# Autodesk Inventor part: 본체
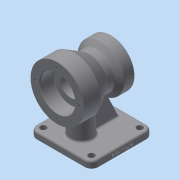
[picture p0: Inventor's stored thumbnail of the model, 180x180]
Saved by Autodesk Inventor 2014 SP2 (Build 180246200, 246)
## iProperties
Created: 2019-01
Part Number: 본체
Material: Generic
Document SubType Name: Modeling
Designer: 거성
Density: 1 g/cm^3
Appearance: Default
Author: 거성
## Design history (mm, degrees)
sketch "스케치1"
  geometry: L1 (44.102, 40)-(44.102, 15); L2 (39.102, -40)-(39.102, -25); L3 (39.102, -25)-(30.944, -18.154); L4 (30.944, -18.154)-(30.944, -7.791); L5 (30.944, -7.791)-(44.102, 15); L6 (20.102, 20)-(20.102, -23); L7 (24.102, -23)-(24.102, -40); L8 (30.102, 20)-(30.102, 40); L9 (4.102, -40)-(4.102, 40); L10 (20.102, -23)-(24.102, -23); L11 (20.102, 20)-(30.102, 20); L12 (30.102, 40)-(44.102, 40); L13 (39.102, -40)-(24.102, -40)
  constraints: 26 end point, 4 parallel, 3 perpendicular, 2 horizontal
  dimensions: "d2" = 25 distance of L1.start L1.end; "d3" = 30 deg angle of L4 L5; "d4" = 15 distance of L2.start L2.end; "d5" = 50 deg angle of L4 L3; "d6" = 52 diameter of L8 L9; "d7" = 32 diameter of L6 L9; "d8" = 40 diameter of L7 L9; "d9" = 80 vertical distance of L2.start L1.start; "d10" = 20 distance of L8.start L8.end; "d11" = 17 distance of L7.start L7.end; "d20" = 80 distance from line of L9.start L12; "d25" = 80 diameter of L1 L9; "d26" = 70 diameter of L2 L9; "d27" = 13.15845 distance between parallel lines of L4 L1; "d28" = 47.14102 distance from line of L9.end L5
revolve "회전1" sketch "스케치1" stored, may be unused: angle "d23" = 90 deg
sketch "스케치2"
  geometry: C1 r 40 at (0, 0) reference; C2 r 26 at (0, 0) reference; 1 further point
sketch "스케치3" dims "d24" = 66
  geometry: L1 (0, 0)-(0, 33); C1 r 26 at (0, 0) reference; 2 further points
  constraints: 2 coincident, 2 end point, 1 vertical, 1 vertical alignment, 2 other
hole "구멍1" sketch "스케치3" at (0, 33) diameter "d29" = 3.242; stored, may be unused: countersink angle "d33" = 90 deg, drill point angle "d35" = 118 deg; dims "d30" = 9, "d31" = 4, "d32" = 2, "d34" = 11
sketch "스케치4" dims "d39" = 55
  geometry: L1 (0, 0)-(0, 27.5); C1 r 35 at (0, 0) reference; 2 further points
  constraints: 2 coincident, 2 end point, 1 vertical, 1 vertical alignment, 2 other
hole "구멍2" sketch "스케치4" at (0, 27.5) diameter "d40" = 3.242; stored, may be unused: countersink angle "d44" = 90 deg, drill point angle "d46" = 118 deg; dims "d41" = 9, "d42" = 4, "d43" = 2, "d45" = 11
node "작업 평면1"
sketch "스케치7"
  geometry: L1 (-70, -36)-(-70, 36) reference; L2 (-70, 0)-(-70, -33.507); 1 further point
  constraints: 2 end point, 1 collinear, 1 midpoint
chamfer "모따기1" distance "d78" = 1; stored, may be unused: second distance "d79" = 2, angle "d80" = 45 deg
fillet "모깎기2" dims "d81" = 1
fillet "모깎기3" dims "d82" = 0.6
sketch "스케치11"
  geometry: L1 (-75.898, 0)-(-75.898, 35); L2 (-75.898, 35)-(-65.898, 35); L3 (-65.898, 35)-(-65.898, -57); L4 (-65.898, -57)-(-75.898, -57); L5 (-75.898, -57)-(-75.898, 0); L6 (-35.898, 40)-(44.102, 40) reference; L7 (44.102, 15)-(30.944, -7.791) reference; L8 (30.944, -7.791)-(30.944, -18.154) reference; L9 (30.944, -18.154)-(39.102, -25) reference; L10 (39.102, -25)-(39.102, -40) reference; L11 (39.102, -40)-(33.223, -40) reference; L12 (33.223, -40)-(33.223, -29) reference; L13 (33.223, -29)-(31.602, -28.026) reference; L14 (31.602, -28.026)-(29.981, -29) reference; L15 (29.981, -29)-(29.981, -40) reference; L16 (29.981, -40)-(25.102, -40) reference; L17 (25.102, -40)-(24.102, -39) reference; L18 (24.102, -39)-(24.102, -23.6) reference; L19 (23.502, -23)-(20.102, -23) reference; L20 (20.102, -23)-(20.102, 20) reference; L21 (20.102, 20)-(29.102, 20) reference; L22 (30.102, 21)-(30.102, 39) reference; L23 (30.102, 39)-(31.102, 40) reference; L24 (31.102, 40)-(35.481, 40) reference; L25 (35.481, 40)-(35.481, 29) reference; L26 (35.481, 29)-(37.102, 28.026) reference; L27 (37.102, 28.026)-(38.723, 29) reference; L28 (38.723, 29)-(38.723, 40) reference; L29 (38.723, 40)-(44.102, 40) reference; L30 (44.102, 40)-(44.102, 15) reference; L31 (-22.739, -7.791)-(-35.898, 15) reference; L32 (-35.898, 15)-(-35.898, 40) reference; L33 (-35.898, 40)-(-30.519, 40) reference; L34 (-30.519, 40)-(-30.519, 29) reference; L35 (-30.519, 29)-(-28.898, 28.026) reference; L36 (-28.898, 28.026)-(-27.277, 29) reference; L37 (-27.277, 29)-(-27.277, 40) reference; L38 (-27.277, 40)-(-22.898, 40) reference; L39 (-22.898, 40)-(-21.898, 39) reference; L40 (-21.898, 39)-(-21.898, 21) reference; L41 (-20.898, 20)-(-11.898, 20) reference; L42 (-11.898, 20)-(-11.898, -23) reference; L43 (-11.898, -23)-(-15.298, -23) reference; L44 (-15.898, -23.6)-(-15.898, -39) reference; L45 (-15.898, -39)-(-16.898, -40) reference; L46 (-16.898, -40)-(-21.777, -40) reference; L47 (-21.777, -40)-(-21.777, -29) reference; L48 (-21.777, -29)-(-23.398, -28.026) reference; L49 (-23.398, -28.026)-(-25.019, -29) reference; L50 (-25.019, -29)-(-25.019, -40) reference; L51 (-25.019, -40)-(-30.898, -40) reference; L52 (-30.898, -40)-(-30.898, -25) reference; L53 (-30.898, -25)-(-22.739, -18.154) reference; L54 (-22.739, -18.154)-(-22.739, -7.791) reference; L55 (31.102, 40)-(-22.898, 40) reference; L56 (4.102, 40)-(4.102, -40); L57 (5.723, -40)-(2.481, -40) reference; L58 (-75.898, 0)-(4.102, 0); A1 r 0.6 centre (23.502, -23.6) between (24.102, -23.6) and (23.502, -23) reference; A2 r 1 centre (29.102, 21) between (29.102, 20) and (30.102, 21) reference; A3 r 1 centre (-20.898, 21) between (-21.898, 21) and (-20.898, 20) reference; A4 r 0.6 centre (-15.298, -23.6) between (-15.298, -23) and (-15.898, -23.6) reference; 1 further point
  constraints: 14 end point, 3 midpoint, 2 parallel, 1 collinear, 1 perpendicular
  dimensions: "d92" = 5 distance between parallel lines of L2 L6; "d93" = 10 distance of L1.end L2.end; "d94" = 92 distance between parallel lines of L4 L2; "d127" = 80 distance of L1.start L58.end
extrude "돌출5" join sketch "스케치11" stored distance "d95" = 92; taper "d96" = 0 deg
sketch "스케치12"
  geometry: L1 (-65.898, -47)-(-16.918, -24.16); L2 (-16.918, -24.16)-(-16.918, -11); L3 (-30.898, -25)-(39.102, -25) reference; L4 (-16.918, -11)-(-65.898, -11); L5 (-65.898, 35)-(-65.898, -57) reference; L6 (-65.898, -47)-(-65.898, -11); L7 (-65.898, -57)-(-75.898, -57) reference; L8 (-65.898, 35)-(-65.898, 5); L9 (-65.898, 5)-(-65.898, -11); 1 further point
  constraints: 12 end point, 2 perpendicular, 2 point on line, 1 collinear, 1 midpoint
  dimensions: "d97" = 10 distance of L1.start L5.end; "d98" = 25 deg angle of L7 L1; "d99" = 48.97999 distance of L2.end L4.end; "d100" = 36 distance of L4.end L1.start; "d128" = 30 distance of L5.start L8.end; "d129" = 16 distance of L8.end L9.end
extrude "돌출6" join sketch "스케치12" stored distance "d101" = 10; taper "d102" = 0 deg
sketch "스케치13"
  geometry: L1 (92, 0)-(0, 0) reference; L2 (0, 0)-(0, 92) reference; C1 r 16 at (46, 30); 1 further point
  constraints: 1 centre point
  dimensions: "d103" = 32 diameter of C1; "d104" = 30 distance from line of L1 C1.centre; "d105" = 46 distance from line of C1.centre L2
extrude "돌출7" join sketch "스케치13" stored distance "d106" = 40; taper "d107" = 0 deg
fillet "모깎기8" dims "d108" = 3
fillet "모깎기9" dims "d109" = 3
fillet "모깎기10" dims "d110" = 3
fillet "모깎기11" dims "d111" = 10
sketch "스케치14"
  geometry: C1 r 4.5 at (0, 82); A1 r 10 centre (0, 82) between (0, 92) and (-10, 82) reference; 1 further point
  constraints: 1 centre point, 1 coincident
  dimensions: "d112" = 9 diameter of C1
extrude "돌출8" cut sketch "스케치14" stored distance "d113" = 10; taper "d114" = 0 deg
fillet "모깎기12" dims "d121" = 3
sketch "스케치15"
  geometry: L1 (-25, -75.898)-(47, -75.898) reference; L2 (-35, -65.898)-(-35, -75.898) reference; 2 further points
  constraints: 1 other
  dimensions: "d122" = 46 distance from line of L2 point (11, -71.898); "d123" = 4 distance from line of L1 point (11, -71.898)
feature "엠보싱2" sketch "스케치15" dims "d124" = 0.5, "d125" = 0
fillet "모깎기13" dims "d126" = 3
sketch "스케치16"
  geometry: L1 (31, 43)-(41, 43); L2 (41, 43)-(41, 41.881); L3 (41, 41.881)-(31, 41.881); L4 (31, 41.881)-(31, 43); 1 further point
  constraints: 8 end point, 2 parallel, 1 horizontal, 1 perpendicular
extrude "돌출9" join sketch "스케치16" distance "d130" = 48; taper "d131" = 0 deg
fillet "모깎기14" dims "d132" = 3
fillet "모깎기15" dims "d133" = 3
fillet "모깎기16" dims "d134" = 3
node "솔리드1"
pattern_circular "원형 패턴1" dims angle "d37" = 360 deg
pattern_circular "원형 패턴2" dims angle "d48" = 360 deg
pattern_linear "직사각형 패턴1" dims "d117" = 72, "d120" = 72
node "절단 모서리 투영1"
